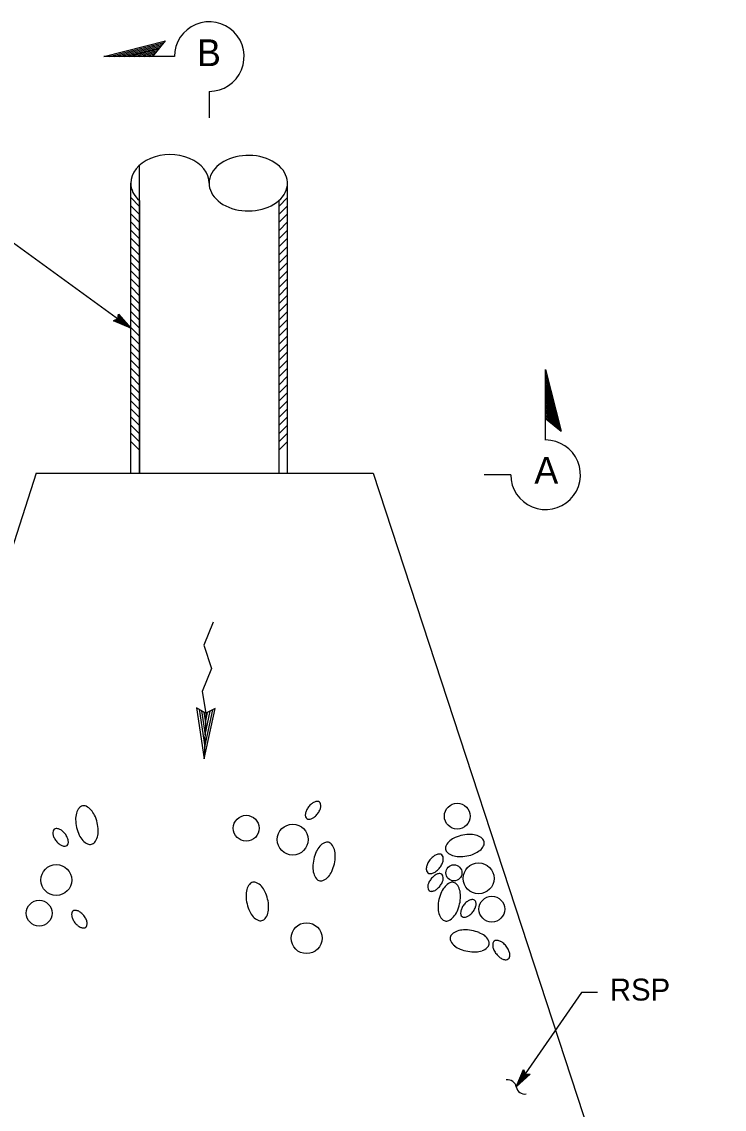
# Model space of a CAD drawing. Extents: x 6707692 to 6708868, y 1870875 to 1871658.
# Drawn here: x 6707908.7 to 6708097.6, y 1871187.6 to 1871480.2 of the extents above; entities that cross this region are included whole.
import ezdxf

# ---------------------------------------------------------------- set-up
doc = ezdxf.new("R2010")
doc.units = 0
doc.layers.add('Level 60', color=7, linetype='Continuous')

msp = doc.modelspace()

# ---------------------------------------------------------------- linework, layer by layer
at = {"layer": 'Level 60'}
for p, q in [((6707930.77, 1871470.87), (6707947.33, 1871475.09)), ((6707932.13, 1871470.87), (6707946.97, 1871474.66)), ((6707943.91, 1871470.87), (6707947.33, 1871475.09)), ((6707933.49, 1871470.87), (6707946.62, 1871474.22)), ((6707934.85, 1871470.87), (6707946.26, 1871473.78)), ((6707936.21, 1871470.87), (6707945.91, 1871473.34)), ((6707937.57, 1871470.87), (6707945.55, 1871472.91)), ((6707938.94, 1871470.87), (6707945.2, 1871472.47)), ((6707940.3, 1871470.87), (6707944.85, 1871472.03)), ((6707941.66, 1871470.87), (6707944.49, 1871471.59)), ((6707949.74, 1871470.87), (6707930.77, 1871470.87)), ((6707943.02, 1871470.87), (6707944.14, 1871471.15)), ((6707949.74, 1871470.95), (6707949.74, 1871470.95)), ((6707959.1, 1871461.5), (6707959.1, 1871454.38)), ((6707940.32, 1871358.74), (6707940.33, 1871441.63)), ((6707937.98, 1871358.74), (6707937.98, 1871436.8)), ((6707937.98, 1871358.74), (6707937.99, 1871436.8)), ((6707980.14, 1871358.74), (6707980.14, 1871436.8)), ((6707940.33, 1871430.56), (6707937.99, 1871432.91)), ((6707940.33, 1871428.39), (6707937.99, 1871430.74)), ((6707940.33, 1871432.1), (6707940.32, 1871358.74)), ((6707977.8, 1871430.56), (6707980.14, 1871432.91)), ((6707977.8, 1871432.1), (6707977.8, 1871358.74)), ((6707977.8, 1871428.39), (6707980.14, 1871430.74)), ((6707940.33, 1871426.2), (6707937.98, 1871428.54)), ((6707977.8, 1871426.2), (6707980.14, 1871428.54)), ((6707940.33, 1871424.01), (6707937.98, 1871426.37)), ((6707977.8, 1871424.01), (6707980.14, 1871426.37)), ((6707940.33, 1871421.83), (6707937.98, 1871424.17)), ((6707940.33, 1871419.65), (6707937.98, 1871421.98)), ((6707977.8, 1871421.83), (6707980.14, 1871424.17)), ((6707977.8, 1871419.65), (6707980.14, 1871421.98)), ((6707940.33, 1871417.46), (6707937.98, 1871419.79)), ((6707977.8, 1871417.46), (6707980.14, 1871419.79)), ((6707940.33, 1871415.27), (6707937.98, 1871417.61)), ((6707977.8, 1871415.27), (6707980.14, 1871417.61)), ((6707940.32, 1871413.09), (6707937.98, 1871415.42)), ((6707940.32, 1871410.89), (6707937.98, 1871413.25)), ((6707977.8, 1871413.09), (6707980.14, 1871415.42)), ((6707977.8, 1871410.89), (6707980.14, 1871413.25)), ((6707940.32, 1871408.71), (6707937.98, 1871411.06)), ((6707977.8, 1871408.71), (6707980.14, 1871411.06)), ((6707940.32, 1871406.53), (6707937.98, 1871408.87)), ((6707977.8, 1871406.53), (6707980.14, 1871408.87)), ((6707940.32, 1871404.34), (6707937.98, 1871406.68)), ((6707940.32, 1871402.15), (6707937.98, 1871404.49)), ((6707977.8, 1871404.34), (6707980.14, 1871406.68)), ((6707977.8, 1871402.15), (6707980.14, 1871404.49)), ((6707934.65, 1871401.55), (6707934.65, 1871401.55)), ((6707940.32, 1871399.97), (6707937.98, 1871402.3)), ((6707977.8, 1871399.97), (6707980.14, 1871402.3)), ((6707933.36, 1871399.78), (6707933.36, 1871399.78)), ((6707940.32, 1871397.78), (6707937.98, 1871400.11)), ((6707977.8, 1871397.78), (6707980.14, 1871400.11)), ((6707940.32, 1871395.6), (6707937.98, 1871397.94)), ((6707937.98, 1871397.77), (6707937.98, 1871397.77)), ((6707940.32, 1871393.42), (6707937.98, 1871395.75)), ((6707977.8, 1871395.6), (6707980.14, 1871397.94)), ((6707977.8, 1871393.42), (6707980.14, 1871395.75)), ((6707940.32, 1871391.23), (6707937.98, 1871393.56)), ((6707977.8, 1871391.23), (6707980.14, 1871393.56)), ((6707940.32, 1871389.04), (6707937.98, 1871391.38)), ((6707977.8, 1871389.04), (6707980.14, 1871391.38)), ((6707940.32, 1871386.85), (6707937.98, 1871389.2)), ((6707940.32, 1871384.66), (6707937.98, 1871387.01)), ((6707977.8, 1871386.85), (6707980.14, 1871389.2)), ((6707977.8, 1871384.66), (6707980.14, 1871387.01)), ((6707940.32, 1871382.48), (6707937.98, 1871384.83)), ((6707977.8, 1871382.48), (6707980.14, 1871384.83)), ((6708049.58, 1871386.66), (6708053.8, 1871370.1)), ((6708049.58, 1871367.69), (6708049.58, 1871386.66)), ((6708049.58, 1871385.3), (6708053.36, 1871370.46)), ((6708049.58, 1871383.94), (6708052.92, 1871370.81)), ((6707940.32, 1871380.29), (6707937.98, 1871382.63)), ((6707977.8, 1871380.29), (6707980.14, 1871382.63)), ((6708049.58, 1871382.58), (6708052.49, 1871371.17)), ((6708049.58, 1871381.22), (6708052.05, 1871371.52)), ((6707940.32, 1871378.12), (6707937.98, 1871380.44)), ((6707940.32, 1871375.93), (6707937.98, 1871378.26)), ((6707977.8, 1871378.12), (6707980.14, 1871380.44)), ((6707977.8, 1871375.93), (6707980.14, 1871378.26)), ((6708049.58, 1871379.86), (6708051.61, 1871371.88)), ((6708049.58, 1871378.49), (6708051.17, 1871372.23)), ((6707940.32, 1871373.74), (6707937.98, 1871376.08)), ((6707977.8, 1871373.74), (6707980.14, 1871376.08)), ((6708049.58, 1871377.13), (6708050.74, 1871372.58)), ((6708049.58, 1871375.77), (6708050.3, 1871372.94)), ((6707940.32, 1871371.55), (6707937.98, 1871373.89)), ((6707977.8, 1871371.55), (6707980.14, 1871373.89)), ((6708049.58, 1871374.41), (6708049.86, 1871373.29)), ((6708049.58, 1871373.52), (6708053.8, 1871370.1)), ((6707940.32, 1871369.36), (6707937.98, 1871371.71)), ((6707940.32, 1871367.17), (6707937.98, 1871369.52)), ((6707977.8, 1871369.36), (6707980.14, 1871371.71)), ((6707977.8, 1871367.17), (6707980.14, 1871369.52)), ((6707940.32, 1871365), (6707937.98, 1871367.33)), ((6707977.8, 1871365), (6707980.14, 1871367.33)), ((6707912.57, 1871358.74), (6707819.35, 1871070.4)), ((6707937.98, 1871358.74), (6707977.8, 1871358.74)), ((6708003.22, 1871358.74), (6708097.63, 1871070.4)), ((6708040.21, 1871358.33), (6708033.08, 1871358.33)), ((6708033.1, 1871358.29), (6708033.1, 1871358.29)), ((6707955.7, 1871295.62), (6707957.76, 1871281.88)), ((6707958.17, 1871294.15), (6707955.7, 1871295.62)), ((6707956.35, 1871295.23), (6707957.87, 1871285.15)), ((6707957.02, 1871294.82), (6707957.97, 1871288.4)), ((6707957.68, 1871294.43), (6707958.08, 1871291.71)), ((6707957.76, 1871281.88), (6707960.71, 1871295.46)), ((6707957.87, 1871285.15), (6707960.04, 1871295.11)), ((6707957.97, 1871288.4), (6707959.34, 1871294.75)), ((6707958.08, 1871291.71), (6707958.66, 1871294.4)), ((6707960.71, 1871295.46), (6707958.17, 1871294.15)), ((6708059.27, 1871218.98), (6708041.69, 1871193.61)), ((6708063.55, 1871218.98), (6708059.27, 1871218.98)), ((6708063.55, 1871218.98), (6708059.27, 1871218.98)), ((6708041.69, 1871193.61), (6708043.6, 1871198.27)), ((6708045.4, 1871197.03), (6708041.69, 1871193.61)), ((6708042.34, 1871194.55), (6708043.73, 1871197.95)), ((6708045.05, 1871197.05), (6708042.34, 1871194.54)), ((6708042.98, 1871195.47), (6708043.88, 1871197.67)), ((6708044.7, 1871197.06), (6708042.98, 1871195.47)), ((6708043.6, 1871198.27), (6708043.6, 1871198.27)), ((6708043.6, 1871198.27), (6708044.12, 1871197.11)), ((6708043.63, 1871196.4), (6708044.01, 1871197.34)), ((6708044.39, 1871197.1), (6708043.63, 1871196.4)), ((6708044.12, 1871197.11), (6708045.4, 1871197.03)), ((6708045.4, 1871197.03), (6708045.4, 1871197.03)), ((6708041.69, 1871193.61), (6708042.72, 1871195.09)), ((6708041.69, 1871193.61), (6708041.69, 1871193.61))]:
    msp.add_line(p, q, dxfattribs=at)
for points in [[(6707860.44, 1871448.01), (6707868.88, 1871448.01), (6707937.98, 1871397.77)], [(6707912.57, 1871358.74), (6708003.22, 1871358.74)], [(6707960.14, 1871318.71), (6707957.6, 1871312.52), (6707959.73, 1871306.19), (6707957.18, 1871300.01), (6707958.17, 1871294.15), (6707957.76, 1871281.88)]]:
    msp.add_lwpolyline(points, dxfattribs=at)
msp.add_lwpolyline([(6707934.65, 1871401.55), (6707937.98, 1871397.77), (6707933.36, 1871399.78), (6707933.67, 1871399.91), (6707937.06, 1871398.44), (6707934.62, 1871401.21), (6707934.59, 1871400.88), (6707936.15, 1871399.1), (6707933.99, 1871400.04), (6707934.3, 1871400.18), (6707935.23, 1871399.77), (6707934.56, 1871400.54), (6707934.53, 1871400.28), (6707933.36, 1871399.78), (6707934.53, 1871400.28)], close=True, dxfattribs=at)
for centre, radius in [((6708025.81, 1871266.48), 3.47), ((6707969.04, 1871263.23), 3.47), ((6707981.55, 1871260.17), 4.16), ((6707917.95, 1871249.28), 4.16), ((6708024.92, 1871251.22), 2.16), ((6708031.55, 1871249.73), 4.16), ((6707913.34, 1871240.38), 3.47), ((6708035.11, 1871241.46), 3.47), ((6707985.29, 1871233.64), 4.16)]:
    msp.add_circle(centre, radius, dxfattribs=at)
for centre, radius, start, end in [((6707959.1, 1871470.87), 9.37, 269.9995, 180), ((6708049.58, 1871358.33), 9.37, 179.9995, 90), ((6707989.78, 1871265.91), 5.01, 129.4192, 142.3114), ((6707988.66, 1871267.27), 3.25, 113.3871, 129.4192), ((6707988.17, 1871268.41), 2.01, 89.1665, 113.3871), ((6707988.18, 1871269.54), 0.886, 52.3114, 89.1665), ((6707988.18, 1871269.54), 0.886, 15.4562, 52.3114), ((6707987.1, 1871269.24), 2.01, 351.2356, 15.4562), ((6707929.43, 1871265.62), 6.29, 165.0482, 180.7625), ((6707927.05, 1871266.26), 3.82, 140.9226, 165.0482), ((6707925.33, 1871267.66), 1.61, 103.3223, 140.9226), ((6707925.33, 1871267.66), 1.61, 65.722, 103.3223), ((6707924.42, 1871265.64), 3.82, 41.5964, 65.722), ((6707922.58, 1871264), 6.29, 25.8821, 41.5964), ((6707919.4, 1871262.46), 9.82, 13.3223, 25.8821), ((6707986.95, 1871266.84), 2.01, 171.2356, 195.4562), ((6707988.18, 1871266.65), 3.25, 155.2035, 171.2356), ((6707989.78, 1871265.91), 5.01, 142.3114, 155.2035), ((6707984.27, 1871270.16), 5.01, 309.4192, 322.3114), ((6707984.27, 1871270.16), 5.01, 322.3114, 335.2035), ((6707985.87, 1871269.42), 3.25, 335.2035, 351.2356), ((6707932.96, 1871265.67), 9.82, 180.7625, 193.3223), ((6707919.4, 1871262.46), 9.82, 0.7625, 13.3223), ((6707985.87, 1871266.54), 0.886, 195.4562, 232.3114), ((6707985.87, 1871266.54), 0.886, 232.3114, 269.1665), ((6707985.88, 1871267.67), 2.01, 269.1665, 293.3871), ((6707985.39, 1871268.8), 3.25, 293.3871, 309.4192), ((6707919.02, 1871261.97), 2.01, 165.2987, 189.5193), ((6707920.24, 1871262.17), 3.25, 189.5193, 205.5514), ((6707917.93, 1871262.25), 0.886, 128.4436, 165.2987), ((6707917.93, 1871262.25), 0.886, 91.5884, 128.4436), ((6707917.96, 1871261.13), 2.01, 67.3678, 91.5884), ((6707917.48, 1871259.99), 3.25, 51.3357, 67.3678), ((6707916.38, 1871258.61), 5.01, 38.4436, 51.3357), ((6707916.38, 1871258.61), 5.01, 25.5514, 38.4436), ((6707932.96, 1871265.67), 9.82, 193.3223, 205.8821), ((6707929.78, 1871264.13), 6.29, 205.8821, 221.5964), ((6707925.31, 1871261.87), 3.82, 320.9226, 345.0482), ((6707922.93, 1871262.51), 6.29, 345.0482, 0.7625), ((6708029.15, 1871251.72), 9.82, 100.6596, 113.2194), ((6708029.15, 1871251.72), 9.82, 88.0998, 100.6596), ((6708029.26, 1871255.25), 6.29, 72.3855, 88.0998), ((6708030.01, 1871257.6), 3.82, 48.2599, 72.3855), ((6707921.83, 1871262.93), 5.01, 205.5514, 218.4436), ((6707921.83, 1871262.93), 5.01, 218.4436, 231.3357), ((6707920.73, 1871261.56), 3.25, 231.3357, 247.3678), ((6707920.25, 1871260.41), 2.01, 247.3678, 271.5884), ((6707920.28, 1871259.29), 0.886, 271.5884, 308.4436), ((6707920.28, 1871259.29), 0.886, 308.4436, 345.2987), ((6707917.97, 1871259.37), 3.25, 9.5193, 25.5514), ((6707919.19, 1871259.57), 2.01, 345.2987, 9.5193), ((6707927.94, 1871262.49), 3.82, 221.5964, 245.722), ((6707927.03, 1871260.47), 1.61, 245.722, 283.3223), ((6707927.03, 1871260.47), 1.61, 283.3223, 320.9226), ((6707993.59, 1871254.25), 6.29, 139.1585, 154.8728), ((6707991.72, 1871255.87), 3.82, 115.0329, 139.1585), ((6707990.79, 1871257.87), 1.61, 77.4326, 115.0329), ((6707990.79, 1871257.87), 1.61, 39.8323, 77.4326), ((6707989.09, 1871256.45), 3.82, 15.7067, 39.8323), ((6708024.23, 1871257.88), 1.61, 153.0594, 190.6596), ((6708026.21, 1871256.88), 3.82, 128.9337, 153.0594), ((6708027.75, 1871254.96), 6.29, 113.2194, 128.9337), ((6708029.51, 1871260.25), 3.82, 308.9337, 333.0594), ((6708031.48, 1871259.25), 1.61, 10.6596, 48.2599), ((6708031.48, 1871259.25), 1.61, 333.0594, 10.6596), ((6707996.79, 1871252.75), 9.82, 154.8728, 167.4326), ((6707986.71, 1871255.79), 6.29, 359.9924, 15.7067), ((6707983.18, 1871255.79), 9.82, 347.4326, 359.9924), ((6708022.8, 1871251.31), 5.51, 129.4192, 142.3114), ((6708021.57, 1871252.81), 3.57, 113.3871, 129.4192), ((6708021.03, 1871254.06), 2.21, 89.1665, 113.3871), ((6708021.05, 1871255.29), 0.975, 52.3114, 89.1665), ((6708021.05, 1871255.29), 0.975, 15.4562, 52.3114), ((6708019.85, 1871254.96), 2.21, 351.2356, 15.4562), ((6708024.23, 1871257.88), 1.61, 190.6596, 228.2599), ((6708025.71, 1871259.54), 3.82, 228.2599, 252.3855), ((6708026.45, 1871261.88), 6.29, 252.3855, 268.0998), ((6708026.57, 1871265.41), 9.82, 268.0998, 280.6596), ((6708026.57, 1871265.41), 9.82, 280.6596, 293.2194), ((6708027.96, 1871262.17), 6.29, 293.2194, 308.9337), ((6707996.79, 1871252.75), 9.82, 167.4326, 179.9924), ((6707993.25, 1871252.75), 6.29, 179.9924, 195.7067), ((6707983.18, 1871255.79), 9.82, 334.8728, 347.4326), ((6708019.69, 1871252.33), 2.21, 171.2356, 195.4562), ((6708021.04, 1871252.12), 3.57, 155.2035, 171.2356), ((6708022.8, 1871251.31), 5.51, 142.3114, 155.2035), ((6708016.75, 1871255.99), 5.51, 309.4192, 322.3114), ((6708016.75, 1871255.99), 5.51, 322.3114, 335.2035), ((6708018.51, 1871255.17), 3.57, 335.2035, 351.2356), ((6707990.88, 1871252.09), 3.82, 195.7067, 219.8323), ((6707989.18, 1871250.67), 1.61, 219.8323, 257.4326), ((6707989.18, 1871250.67), 1.61, 257.4326, 295.0329), ((6707988.24, 1871252.68), 3.82, 295.0329, 319.1585), ((6707986.38, 1871254.29), 6.29, 319.1585, 334.8728), ((6708018.5, 1871252), 0.975, 195.4562, 232.3114), ((6708018.5, 1871252), 0.975, 232.3114, 269.1665), ((6708022.71, 1871246.5), 5.01, 142.3114, 155.2035), ((6708018.52, 1871253.24), 2.21, 269.1665, 293.3871), ((6708022.71, 1871246.5), 5.01, 129.4192, 142.3114), ((6708017.98, 1871254.49), 3.57, 293.3871, 309.4192), ((6708021.59, 1871247.86), 3.25, 113.3871, 129.4192), ((6708021.1, 1871249), 2.01, 89.1665, 113.3871), ((6708021.12, 1871250.13), 0.886, 52.3114, 89.1665), ((6708021.12, 1871250.13), 0.886, 15.4562, 52.3114), ((6708018.81, 1871250.01), 3.25, 335.2035, 351.2356), ((6708020.03, 1871249.83), 2.01, 351.2356, 15.4562), ((6707975.28, 1871245.08), 6.29, 165.0482, 180.7625), ((6707972.9, 1871245.71), 3.82, 140.9226, 165.0482), ((6707971.18, 1871247.11), 1.61, 103.3223, 140.9226), ((6707971.18, 1871247.11), 1.61, 65.722, 103.3223), ((6707970.27, 1871245.09), 3.82, 41.5964, 65.722), ((6707968.42, 1871243.46), 6.29, 25.8821, 41.5964), ((6708019.89, 1871247.43), 2.01, 171.2356, 195.4562), ((6708021.11, 1871247.24), 3.25, 155.2035, 171.2356), ((6708018.8, 1871247.13), 0.886, 195.4562, 232.3114), ((6708018.8, 1871247.13), 0.886, 232.3114, 269.1665), ((6708018.82, 1871248.26), 2.01, 269.1665, 293.3871), ((6708018.33, 1871249.39), 3.25, 293.3871, 309.4192), ((6708017.21, 1871250.75), 5.01, 309.4192, 322.3114), ((6708017.21, 1871250.75), 5.01, 322.3114, 335.2035), ((6708027.28, 1871243.45), 6.29, 139.1585, 154.8728), ((6708025.41, 1871245.06), 3.82, 115.0329, 139.1585), ((6708024.48, 1871247.07), 1.61, 77.4326, 115.0329), ((6708024.48, 1871247.07), 1.61, 39.8323, 77.4326), ((6708022.78, 1871245.65), 3.82, 15.7067, 39.8323), ((6708020.4, 1871244.98), 6.29, 359.9924, 15.7067), ((6707978.81, 1871245.13), 9.82, 180.7625, 193.3223), ((6707965.25, 1871241.91), 9.82, 13.3223, 25.8821), ((6707965.25, 1871241.91), 9.82, 0.7625, 13.3223), ((6708030.48, 1871241.95), 9.82, 167.4326, 179.9924), ((6708030.48, 1871241.95), 9.82, 154.8728, 167.4326), ((6708016.87, 1871244.98), 9.82, 347.4326, 359.9924), ((6708031.55, 1871239.53), 5.01, 129.4192, 142.3114), ((6708030.43, 1871240.89), 3.25, 113.3871, 129.4192), ((6708029.94, 1871242.03), 2.01, 89.1665, 113.3871), ((6708029.95, 1871243.15), 0.886, 52.3114, 89.1665), ((6708029.95, 1871243.15), 0.886, 15.4562, 52.3114), ((6708028.87, 1871242.85), 2.01, 351.2356, 15.4562), ((6707924.08, 1871239.95), 2.01, 165.2987, 189.5193), ((6707922.99, 1871240.24), 0.886, 128.4436, 165.2987), ((6707922.99, 1871240.24), 0.886, 91.5884, 128.4436), ((6707923.02, 1871239.11), 2.01, 67.3678, 91.5884), ((6707922.55, 1871237.97), 3.25, 51.3357, 67.3678), ((6707921.44, 1871236.59), 5.01, 38.4436, 51.3357), ((6707978.81, 1871245.13), 9.82, 193.3223, 205.8821), ((6707975.63, 1871243.58), 6.29, 205.8821, 221.5964), ((6707968.78, 1871241.96), 6.29, 345.0482, 0.7625), ((6708026.94, 1871241.95), 6.29, 179.9924, 195.7067), ((6708020.07, 1871243.48), 6.29, 319.1585, 334.8728), ((6708016.87, 1871244.98), 9.82, 334.8728, 347.4326), ((6708028.72, 1871240.46), 2.01, 171.2356, 195.4562), ((6708029.95, 1871240.27), 3.25, 155.2035, 171.2356), ((6708031.55, 1871239.53), 5.01, 142.3114, 155.2035), ((6708026.04, 1871243.78), 5.01, 309.4192, 322.3114), ((6708026.04, 1871243.78), 5.01, 322.3114, 335.2035), ((6708027.65, 1871243.04), 3.25, 335.2035, 351.2356), ((6707925.3, 1871240.15), 3.25, 189.5193, 205.5514), ((6707926.89, 1871240.92), 5.01, 205.5514, 218.4436), ((6707926.89, 1871240.92), 5.01, 218.4436, 231.3357), ((6707921.44, 1871236.59), 5.01, 25.5514, 38.4436), ((6707923.04, 1871237.35), 3.25, 9.5193, 25.5514), ((6707924.26, 1871237.56), 2.01, 345.2987, 9.5193), ((6707973.79, 1871241.95), 3.82, 221.5964, 245.722), ((6707972.88, 1871239.93), 1.61, 245.722, 283.3223), ((6707972.88, 1871239.93), 1.61, 283.3223, 320.9226), ((6707971.16, 1871241.32), 3.82, 320.9226, 345.0482), ((6708024.57, 1871241.28), 3.82, 195.7067, 219.8323), ((6708022.87, 1871239.86), 1.61, 219.8323, 257.4326), ((6708022.87, 1871239.86), 1.61, 257.4326, 295.0329), ((6708021.93, 1871241.87), 3.82, 295.0329, 319.1585), ((6708027.64, 1871240.16), 0.886, 195.4562, 232.3114), ((6708027.64, 1871240.16), 0.886, 232.3114, 269.1665), ((6708027.66, 1871241.28), 2.01, 269.1665, 293.3871), ((6708027.16, 1871242.42), 3.25, 293.3871, 309.4192), ((6707925.79, 1871239.54), 3.25, 231.3357, 247.3678), ((6707925.31, 1871238.4), 2.01, 247.3678, 271.5884), ((6707925.34, 1871237.27), 0.886, 271.5884, 308.4436), ((6707925.34, 1871237.27), 0.886, 308.4436, 345.2987), ((6708025.51, 1871233.55), 1.61, 132.495, 170.0953), ((6708027.01, 1871231.91), 3.82, 108.3694, 132.495), ((6708027.79, 1871229.58), 6.29, 92.6551, 108.3694), ((6708027.95, 1871226.05), 9.82, 80.0953, 92.6551), ((6708027.95, 1871226.05), 9.82, 67.5355, 80.0953), ((6708029.3, 1871229.31), 6.29, 51.8212, 67.5355), ((6708025.51, 1871233.55), 1.61, 170.0953, 207.6956), ((6708027.48, 1871234.58), 3.82, 207.6956, 231.8212), ((6708030.82, 1871231.25), 3.82, 27.6956, 51.8212), ((6708032.78, 1871232.28), 1.61, 312.495, 350.0953), ((6708032.78, 1871232.28), 1.61, 350.0953, 27.6956), ((6708037.55, 1871231.77), 2.21, 165.2987, 189.5193), ((6708036.35, 1871232.08), 0.975, 128.4436, 165.2987), ((6708036.35, 1871232.08), 0.975, 91.5884, 128.4436), ((6708036.38, 1871230.84), 2.21, 67.3678, 91.5884), ((6708035.86, 1871229.59), 3.57, 51.3357, 67.3678), ((6708034.65, 1871228.07), 5.51, 38.4436, 51.3357), ((6708029, 1871236.51), 6.29, 231.8212, 247.5355), ((6708030.35, 1871239.78), 9.82, 247.5355, 260.0953), ((6708030.35, 1871239.78), 9.82, 260.0953, 272.6551), ((6708030.51, 1871236.25), 6.29, 272.6551, 288.3694), ((6708031.29, 1871233.91), 3.82, 288.3694, 312.495), ((6708038.89, 1871231.99), 3.57, 189.5193, 205.5514), ((6708040.64, 1871232.83), 5.51, 205.5514, 218.4436), ((6708040.64, 1871232.83), 5.51, 218.4436, 231.3357), ((6708034.65, 1871228.07), 5.51, 25.5514, 38.4436), ((6708036.4, 1871228.91), 3.57, 9.5193, 25.5514), ((6708037.74, 1871229.13), 2.21, 345.2987, 9.5193), ((6708039.43, 1871231.31), 3.57, 231.3357, 247.3678), ((6708038.9, 1871230.06), 2.21, 247.3678, 271.5884), ((6708038.94, 1871228.82), 0.975, 271.5884, 308.4436), ((6708038.94, 1871228.82), 0.975, 308.4436, 345.2987), ((6708039.41, 1871193.2), 2.32, 10.2849, 100.2849), ((6708043.97, 1871194.03), 2.32, 190.2849, 280.2849)]:
    msp.add_arc(centre, radius, start, end, dxfattribs=at)
for centre, major_axis, ratio, start_param, end_param in [((6707948.52, 1871436.79), (10.54, 0), 0.730091, 0, 3.141593), ((6707969.6, 1871436.8), (10.54, 0), 0.709759, 6.23222, 11.886701), ((6707948.52, 1871436.8), (-10.54, 0), 0.709759, 0.000058, 0.679669), ((6707969.6, 1871436.8), (10.54, 0), 0.709759, 5.603516, 6.283127)]:
    msp.add_ellipse(centre, major_axis=major_axis, ratio=ratio, start_param=start_param, end_param=end_param, dxfattribs=at)

# ---------------------------------------------------------------- texts
for s, height, p in [('B', 7.21, (6707955.79, 1871468.29)), ('A', 7.21, (6708046.55, 1871355.95)), ('RSP', 5.9, (6708066.86, 1871216.86))]:
    msp.add_text(s, height=height, dxfattribs=at).set_placement(p)

doc.saveas('drawing.dxf')
